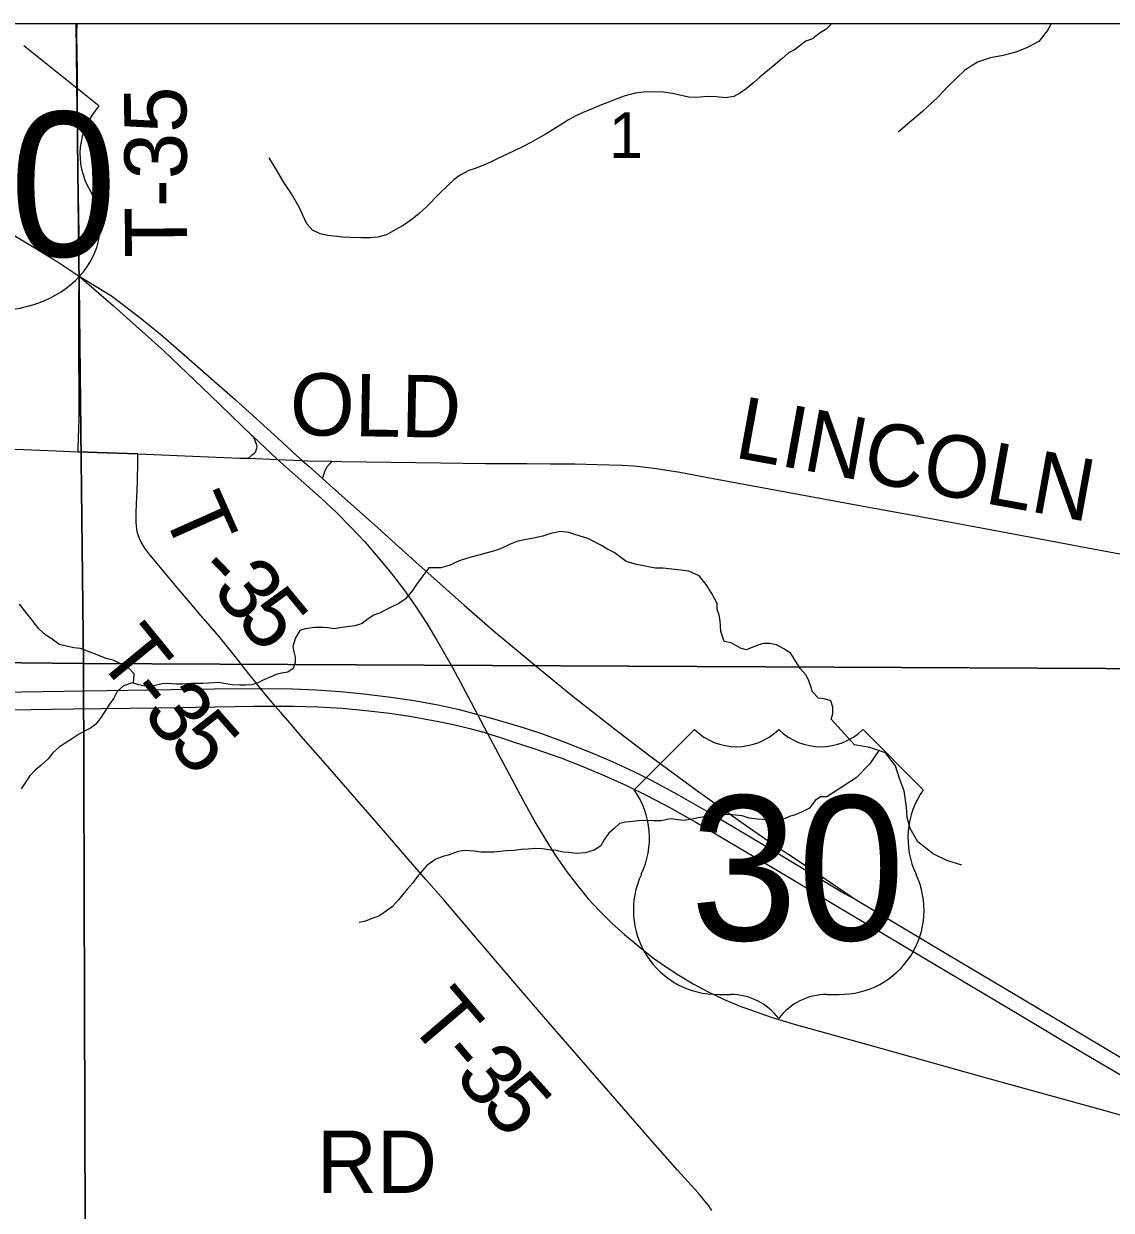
# Model space of a CAD drawing. Extents: x 0 to 34, y 0 to 22.
# Drawn here: x 4.726 to 5.719, y 19.817 to 20.9 of the extents above; entities that cross this region are included whole.
import ezdxf

# ---------------------------------------------------------------- set-up
doc = ezdxf.new("R2010")
doc.units = 0
for name, color, linetype in [('GM_X_County_Road', 7, 'Continuous'), ('GM_X_County_Road_Text', 7, 'Continuous'), ('GM_X_Interchange_Ramps', 7, 'Continuous'), ('GM_X_Minor_River', 7, 'Continuous'), ('GM_X_Section', 7, 'Continuous'), ('GM_X_Section_Text', 7, 'Continuous'), ('GM_X_Township_Road', 7, 'Continuous'), ('GM_X_Township_Road_Text', 7, 'Continuous'), ('GM_X_Unincorporated', 7, 'Continuous'), ('GM_X_US_Location', 7, 'Continuous'), ('GM_X_US_Route', 7, 'Continuous'), ('GM_X_US_Shield', 7, 'Continuous')]:
    doc.layers.add(name, color=color, linetype=linetype)

msp = doc.modelspace()

# ---------------------------------------------------------------- linework, layer by layer
at = {"layer": 'GM_X_County_Road'}
msp.add_line((4.9312, 20.5034), (4.9578, 20.5024), dxfattribs=at)
for points in [[(4.283, 20.4469), (4.286, 20.4472), (4.2983, 20.4487), (4.3168, 20.4517), (4.3473, 20.4574), (4.4482, 20.4752), (4.4727, 20.4795), (4.5308, 20.4898), (4.6012, 20.5021), (4.6318, 20.5072), (4.6503, 20.5097), (4.6657, 20.5113), (4.6812, 20.5121), (4.6967, 20.5123), (4.7184, 20.5117), (4.7556, 20.5101), (4.7757, 20.5094)], [(4.7757, 20.5094), (4.7929, 20.5087), (4.8304, 20.5074)], [(4.8304, 20.5074), (4.8519, 20.5066), (4.9233, 20.5036), (4.9312, 20.5034)], [(4.9578, 20.5024), (4.9802, 20.5013), (4.9853, 20.5011), (5.0077, 20.5007)], [(5.0077, 20.5007), (5.0164, 20.5005), (5.1065, 20.4993), (5.1476, 20.4987), (5.1695, 20.4986)], [(5.1695, 20.4986), (5.1854, 20.4986), (5.2065, 20.4983), (5.2294, 20.4982), (5.2496, 20.4977), (5.2723, 20.4972), (5.283, 20.4965), (5.2939, 20.4954), (5.3034, 20.4942), (5.3248, 20.4906), (5.3554, 20.485), (5.5022, 20.458), (5.5359, 20.4518), (5.6032, 20.4392), (5.6277, 20.4348), (5.7314, 20.4153), (5.7741, 20.4072), (5.7768, 20.4067)]]:
    msp.add_lwpolyline(points, dxfattribs=at)
at = {"layer": 'GM_X_Interchange_Ramps'}
for points in [[(4.9357, 20.5231), (4.937, 20.5197), (4.9383, 20.5165), (4.9388, 20.5142), (4.9385, 20.5124), (4.9375, 20.5095), (4.9358, 20.5072), (4.9341, 20.5058), (4.9312, 20.5034)], [(4.9989, 20.4848), (4.9994, 20.4865), (5.001, 20.4916), (5.0021, 20.494), (5.0034, 20.4961), (5.0057, 20.4985), (5.0077, 20.5007)]]:
    msp.add_lwpolyline(points, dxfattribs=at)
at = {"layer": 'GM_X_Minor_River'}
for points in [[(5.4632, 20.9), (5.4585, 20.8951), (5.452, 20.8909), (5.446, 20.8863), (5.4399, 20.884), (5.4297, 20.876), (5.424, 20.8733), (5.418, 20.868), (5.4101, 20.8611), (5.4033, 20.8557), (5.398, 20.8511), (5.3923, 20.8462), (5.3855, 20.8404), (5.3802, 20.837), (5.3741, 20.8335), (5.3666, 20.8324), (5.3582, 20.8331), (5.3499, 20.8334), (5.3434, 20.833), (5.3343, 20.8326), (5.3275, 20.8341), (5.3183, 20.8363), (5.31, 20.8374), (5.3009, 20.8378), (5.2922, 20.8374), (5.2842, 20.8366), (5.2751, 20.8342), (5.2675, 20.8315), (5.2607, 20.8288), (5.2535, 20.8258), (5.2455, 20.8227), (5.2368, 20.8188), (5.23, 20.8158), (5.2232, 20.8123), (5.2156, 20.8073), (5.2085, 20.8028), (5.202, 20.7989), (5.196, 20.7955), (5.1895, 20.792), (5.182, 20.7878), (5.1744, 20.7843), (5.1672, 20.7809), (5.1589, 20.7771), (5.1521, 20.7736), (5.1452, 20.7705), (5.138, 20.7678), (5.1324, 20.7659), (5.1244, 20.7617), (5.1191, 20.7579), (5.1127, 20.7517), (5.1059, 20.7453), (5.0938, 20.733), (5.087, 20.7269), (5.0802, 20.7212), (5.0723, 20.7158), (5.0651, 20.712), (5.0571, 20.7074), (5.0492, 20.7051), (5.0424, 20.7047), (5.034, 20.7046), (5.0241, 20.705), (5.0173, 20.7053), (5.012, 20.7057), (5.0036, 20.7068), (4.9968, 20.7083), (4.9896, 20.7116)], [(5.6634, 20.9), (5.6611, 20.8948), (5.6525, 20.8838), (5.6408, 20.8776), (5.6306, 20.8738), (5.62, 20.871), (5.6083, 20.8687), (5.5966, 20.8648), (5.5849, 20.8575), (5.5698, 20.843), (5.5601, 20.8326), (5.5465, 20.82), (5.5367, 20.8116), (5.5243, 20.8009)], [(4.9896, 20.7116), (4.9844, 20.7172), (4.9775, 20.7327), (4.9706, 20.7448), (4.9633, 20.7558), (4.9568, 20.7667), (4.95, 20.7777)], [(5.4842, 20.242), (5.4629, 20.2652), (5.4644, 20.2701), (5.4647, 20.2762), (5.4628, 20.2819), (5.4567, 20.2838), (5.4514, 20.2845), (5.446, 20.2902), (5.4445, 20.2951), (5.4426, 20.3004), (5.4403, 20.3054), (5.4349, 20.3111), (5.4307, 20.3179), (5.4261, 20.3251), (5.4204, 20.3292), (5.4132, 20.333), (5.4067, 20.3345), (5.4014, 20.3345), (5.3961, 20.3329), (5.3908, 20.3306), (5.3855, 20.3287), (5.3802, 20.3302), (5.3718, 20.3351), (5.3653, 20.3362), (5.3623, 20.3453), (5.3618, 20.3552), (5.3607, 20.3601), (5.3591, 20.3655), (5.3591, 20.3708), (5.3541, 20.3799), (5.3488, 20.3882), (5.3426, 20.3962), (5.3331, 20.4003), (5.3259, 20.4014), (5.3176, 20.4021), (5.3096, 20.4032), (5.3028, 20.4032), (5.2978, 20.404), (5.2902, 20.4054), (5.2853, 20.4066), (5.2758, 20.4092), (5.2651, 20.4175), (5.2583, 20.4209), (5.2533, 20.4239), (5.2408, 20.4303), (5.229, 20.4337), (5.2237, 20.4356), (5.2161, 20.4367), (5.2073, 20.4347), (5.1998, 20.4324), (5.1914, 20.4305), (5.185, 20.4293), (5.177, 20.4277), (5.1694, 20.4247), (5.1611, 20.4208), (5.1558, 20.4189), (5.149, 20.417), (5.1414, 20.415), (5.1334, 20.4127), (5.1262, 20.4108), (5.1213, 20.4089), (5.1153, 20.4058), (5.1069, 20.4035), (5.0959, 20.4034), (5.0895, 20.395), (5.0846, 20.3882), (5.0808, 20.3828), (5.0741, 20.3748), (5.0684, 20.371), (5.0616, 20.3675), (5.0567, 20.3652), (5.0514, 20.3625), (5.0457, 20.3602), (5.0404, 20.3568), (5.0351, 20.3526), (5.0283, 20.3506), (5.0211, 20.3495), (5.0146, 20.3487), (5.0097, 20.3479), (5.004, 20.3486), (4.9991, 20.349), (4.9915, 20.3489), (4.9831, 20.3478), (4.9782, 20.3462), (4.9741, 20.3394), (4.9718, 20.3317), (4.9726, 20.3268), (4.9738, 20.3219), (4.9738, 20.3169), (4.9719, 20.3116), (4.967, 20.3082), (4.9613, 20.3074), (4.9564, 20.3062), (4.9515, 20.3039), (4.9454, 20.3012)], [(4.8264, 20.298), (4.827, 20.3068), (4.8216, 20.3121), (4.8155, 20.3151), (4.8076, 20.3192), (4.8015, 20.3207), (4.7946, 20.3233), (4.7844, 20.3275), (4.7779, 20.3297), (4.7718, 20.3305), (4.765, 20.3319), (4.7585, 20.3334), (4.7517, 20.3387), (4.7463, 20.3421), (4.7398, 20.3478), (4.7337, 20.3558), (4.7223, 20.3702)], [(4.9454, 20.3012), (4.9397, 20.2985), (4.9344, 20.2966), (4.9287, 20.2962), (4.9234, 20.2962), (4.9162, 20.2965), (4.9109, 20.2976), (4.9041, 20.2987), (4.8946, 20.2983), (4.8896, 20.2979), (4.879, 20.2979), (4.8707, 20.2974), (4.8654, 20.2974), (4.8574, 20.2978), (4.8524, 20.2977), (4.8445, 20.2958), (4.8365, 20.2954), (4.8312, 20.2965), (4.8251, 20.2984), (4.8172, 20.2957), (4.8115, 20.2907), (4.8085, 20.2846), (4.8043, 20.2789), (4.801, 20.2739), (4.7968, 20.2671), (4.7919, 20.2606), (4.787, 20.2571), (4.7821, 20.2548), (4.776, 20.2514), (4.7696, 20.2472), (4.7639, 20.2434), (4.7586, 20.2399), (4.7526, 20.2346), (4.7484, 20.2292), (4.7416, 20.2231), (4.7367, 20.2189), (4.7314, 20.2132), (4.7281, 20.2082), (4.7239, 20.2017)], [(5.5823, 20.132), (5.5686, 20.1364), (5.5561, 20.1424), (5.542, 20.1533), (5.5351, 20.1654), (5.5324, 20.1756), (5.5319, 20.1851), (5.5296, 20.1999), (5.5257, 20.2104), (5.5218, 20.2226), (5.5127, 20.2346), (5.4982, 20.2394), (5.4842, 20.242)], [(5.5065, 20.2367), (5.498, 20.2243), (5.4859, 20.2117)], [(5.4859, 20.2117), (5.4591, 20.1944), (5.4534, 20.1944), (5.4485, 20.191), (5.4432, 20.1841), (5.436, 20.1803), (5.4303, 20.178), (5.425, 20.1764), (5.4189, 20.1737), (5.4125, 20.1729), (5.4064, 20.1729), (5.4007, 20.1736), (5.3954, 20.174), (5.3882, 20.1751), (5.3817, 20.177), (5.3757, 20.1777), (5.3688, 20.1784), (5.362, 20.1776), (5.3533, 20.1765), (5.3476, 20.1761), (5.3415, 20.1753), (5.3347, 20.1737), (5.3282, 20.1729), (5.3161, 20.1744), (5.3078, 20.1725), (5.3009, 20.1724), (5.2937, 20.1728), (5.2873, 20.1724), (5.2816, 20.172), (5.2755, 20.1712), (5.2698, 20.17), (5.2649, 20.1654), (5.26, 20.1612), (5.2562, 20.1559), (5.2528, 20.1498), (5.2468, 20.1459), (5.2388, 20.1432), (5.2305, 20.1428), (5.2237, 20.1436), (5.2183, 20.1439), (5.2119, 20.1454), (5.2069, 20.1458), (5.1997, 20.1469), (5.1933, 20.1472), (5.1864, 20.1468), (5.18, 20.1464), (5.1736, 20.1456), (5.1663, 20.1452), (5.1607, 20.1444), (5.1553, 20.144), (5.1436, 20.144), (5.1371, 20.1447), (5.128, 20.1454), (5.1227, 20.1446), (5.1136, 20.1412), (5.1087, 20.14), (5.1022, 20.1377), (5.0939, 20.1319), (5.0898, 20.127), (5.0853, 20.1213), (5.0811, 20.1159), (5.0762, 20.1102), (5.0721, 20.1052), (5.0683, 20.1003), (5.0626, 20.0945), (5.0551, 20.0888), (5.0501, 20.0854), (5.0433, 20.083), (5.038, 20.0811), (5.0323, 20.0796)]]:
    msp.add_lwpolyline(points, dxfattribs=at)
at = {"layer": 'GM_X_Section'}
for points in [[(4.783, 19.4891), (4.7808, 20.316), (3.7817, 20.3267), (3.7715, 19.4891)], [(5.415, 19.3104), (5.7798, 19.3134), (5.776, 20.2897), (5.7762, 20.3113), (4.7808, 20.316), (4.783, 19.4891), (5.415, 19.4891)]]:
    msp.add_lwpolyline(points, close=True, dxfattribs=at)
at = {"layer": 'GM_X_Township_Road'}
for points in [[(5.7764, 19.7938), (5.7766, 19.8909), (5.7765, 19.9131), (5.7764, 19.9288), (5.7766, 20.4072), (5.7818, 20.9), (2.1, 20.9)], [(4.7766, 20.6695), (4.7767, 20.7042), (4.7763, 20.7289), (4.7756, 20.7665), (4.7754, 20.7877), (4.7751, 20.8136), (4.7751, 20.8441), (4.7751, 20.858), (4.775, 20.8723), (4.7747, 20.8907), (4.7748, 20.9)], [(4.7757, 20.5094), (4.7758, 20.513), (4.7766, 20.5394), (4.7763, 20.6202), (4.7763, 20.6481), (4.7766, 20.6666), (4.7766, 20.6695)], [(4.8304, 20.5074), (4.7929, 20.5087), (4.7757, 20.5094)], [(4.9557, 20.2771), (4.9422, 20.2932), (4.9354, 20.3017), (4.9317, 20.3067), (4.9182, 20.3238), (4.9044, 20.3406), (4.8882, 20.3595), (4.8661, 20.3855), (4.8521, 20.4021), (4.8402, 20.4165), (4.8365, 20.4215), (4.8334, 20.4269), (4.832, 20.4297), (4.831, 20.4326), (4.8301, 20.4355), (4.8294, 20.4386), (4.8288, 20.4448), (4.8288, 20.4541), (4.83, 20.482), (4.8303, 20.5007), (4.8304, 20.5074)], [(5.354, 19.8169), (5.3532, 19.8184), (5.3523, 19.8198), (5.3516, 19.821), (5.3496, 19.8234), (5.3415, 19.8329), (5.3228, 19.8537), (5.2982, 19.8817), (5.2615, 19.9238), (5.237, 19.9519), (5.2227, 19.9683), (5.2044, 19.9894), (5.1761, 20.0224), (5.1337, 20.072), (5.1095, 20.1003), (5.0931, 20.1189), (5.0808, 20.1329), (5.0545, 20.1636), (5.0362, 20.1846), (5.0218, 20.201), (5.0036, 20.2221), (4.9811, 20.2478), (4.969, 20.262), (4.9609, 20.2714), (4.9557, 20.2771)]]:
    msp.add_lwpolyline(points, dxfattribs=at)
at = {"layer": 'GM_X_Unincorporated'}
for points in [[(4.7739, 20.9), (3.785, 20.9), (3.7817, 20.3267), (4.7808, 20.316)], [(5.7777, 20.9), (4.7739, 20.9), (4.7808, 20.316), (5.7762, 20.3113)]]:
    msp.add_lwpolyline(points, close=True, dxfattribs=at)
at = {"layer": 'GM_X_US_Route'}
for points in [[(4.258, 20.9), (4.2837, 20.89), (4.4135, 20.8396), (4.4602, 20.8211), (4.5062, 20.8035), (4.5612, 20.7819), (4.5956, 20.7677), (4.6184, 20.7577), (4.6437, 20.7459), (4.6684, 20.7334), (4.6879, 20.7233), (4.712, 20.7099), (4.7362, 20.6954), (4.7574, 20.6823), (4.772, 20.6725), (4.7766, 20.6695)], [(4.7766, 20.6695), (4.808, 20.6426), (4.8288, 20.6241), (4.8539, 20.6015), (4.8962, 20.5609), (4.9341, 20.5245), (4.9357, 20.5231), (4.9511, 20.5087), (4.9578, 20.5024), (4.9979, 20.4666), (5.0115, 20.4538), (5.0247, 20.4406), (5.0374, 20.427), (5.0497, 20.4129), (5.0616, 20.3985), (5.0729, 20.3836), (5.0836, 20.3683), (5.0939, 20.3527), (5.1035, 20.3367), (5.1173, 20.3124), (5.1316, 20.2857)], [(4.7766, 20.6695), (4.8062, 20.6515), (4.832, 20.632), (4.8511, 20.6165), (4.8676, 20.602), (4.919, 20.5569), (4.9579, 20.5218), (4.9751, 20.506), (4.9802, 20.5013), (4.9865, 20.4959), (4.9989, 20.4848), (5.0051, 20.4792), (5.0492, 20.4398), (5.0839, 20.4086), (5.1281, 20.3692), (5.1564, 20.3447), (5.1971, 20.3108), (5.2261, 20.2873), (5.2654, 20.2566), (5.2976, 20.232), (5.3402, 20.2005), (5.3807, 20.1715), (5.4064, 20.1538), (5.4406, 20.1313), (5.4849, 20.1009)], [(4.7043, 20.2901), (4.782, 20.2912), (4.9, 20.2929), (4.9422, 20.2932), (4.9435, 20.2932), (4.9715, 20.2929), (4.9932, 20.292), (5.0149, 20.2906), (5.0365, 20.2885), (5.0611, 20.2855), (5.0826, 20.2822), (5.104, 20.2783), (5.1222, 20.2744), (5.1282, 20.273), (5.1402, 20.2697), (5.1462, 20.2681), (5.1581, 20.2647), (5.1819, 20.2576), (5.1996, 20.2518), (5.22, 20.2444), (5.2431, 20.2353), (5.2631, 20.2268), (5.2829, 20.2177), (5.2995, 20.2093), (5.3241, 20.196), (5.3537, 20.179), (5.41, 20.1456), (5.4753, 20.1063), (5.4849, 20.1009), (5.5695, 20.0507), (5.6521, 20.0015), (5.7321, 19.9538)], [(5.1316, 20.2857), (5.1402, 20.2697), (5.1495, 20.2523), (5.1816, 20.1917), (5.1936, 20.17), (5.2031, 20.154), (5.2114, 20.1409), (5.2221, 20.1257), (5.2315, 20.1134), (5.2414, 20.1015), (5.2519, 20.09), (5.2629, 20.0791), (5.2743, 20.0687), (5.2886, 20.0568), (5.3008, 20.0473), (5.3109, 20.0401), (5.3239, 20.0316), (5.3372, 20.0238), (5.3509, 20.0165), (5.3649, 20.0099), (5.3792, 20.0038), (5.3937, 19.9984), (5.4084, 19.9934), (5.4292, 19.9871), (5.4919, 19.9695), (5.6056, 19.9378), (5.7094, 19.9091), (5.7352, 19.9018)], [(4.6749, 20.2733), (4.7712, 20.2746), (4.8489, 20.2756), (4.9359, 20.2771), (4.9557, 20.2771), (4.9573, 20.2771), (4.9732, 20.2771), (4.9949, 20.2766), (5.0167, 20.2753), (5.0384, 20.2733), (5.06, 20.2707), (5.0784, 20.2679), (5.0999, 20.2641), (5.1047, 20.2631)], [(5.1047, 20.2631), (5.1182, 20.2603), (5.1333, 20.2568), (5.1444, 20.2539)], [(5.1444, 20.2539), (5.1454, 20.2536), (5.1495, 20.2523), (5.1602, 20.2489), (5.172, 20.245), (5.1927, 20.2383), (5.2162, 20.23), (5.2365, 20.2222), (5.2565, 20.2137), (5.2763, 20.2047), (5.2959, 20.1951), (5.3151, 20.1849), (5.3395, 20.1712), (5.4224, 20.1222), (5.4704, 20.0934), (5.636, 19.9949), (5.6893, 19.963), (5.7483, 19.9284), (5.7726, 19.9147), (5.7767, 19.9125)]]:
    msp.add_lwpolyline(points, dxfattribs=at)
at = {"layer": 'GM_X_US_Shield'}
for p, q in [((4.7948, 20.8249), (4.7261, 20.8799)), ((5.3382, 20.2558), (5.2833, 20.2009)), ((5.547, 20.2009), (5.4921, 20.2558)), ((5.3602, 20.0141), (5.3712, 20.0141)), ((5.4591, 20.0141), (5.4701, 20.0141))]:
    msp.add_line(p, q, dxfattribs=at)
for centre, radius, start, end in [((5.3767, 20.2951), 0.0549, 225.573, 314.427), ((5.4536, 20.2951), 0.0549, 225.573, 314.427), ((5.2203, 20.1568), 0.0769, 334.5471, 35.0009), ((5.61, 20.1568), 0.0769, 144.9991, 205.4529), ((5.3594, 20.091), 0.0769, 154.8319, 270.6383), ((5.4709, 20.091), 0.0769, 269.3617, 25.1681), ((5.3712, 19.9592), 0.0549, 36.8699, 90), ((5.4591, 19.9592), 0.0549, 90, 143.1301)]:
    msp.add_arc(centre, radius, start, end, dxfattribs=at)
for centre, start_param, end_param in [((4.8735, 20.7808), 5.672304, 6.727422), ((4.6997, 20.7151), 1.559657, 3.580859)]:
    msp.add_ellipse(centre, major_axis=(-0.0961, 0), ratio=0.8, start_param=start_param, end_param=end_param, dxfattribs=at)

# ---------------------------------------------------------------- texts
at = {"layer": 'GM_X_County_Road_Text'}
for s, rotation, p in [('OLD', 359.0196, (4.9687, 20.5246)), ('LINCOLN', 349.667, (5.3734, 20.5043))]:
    msp.add_text(s, height=0.05682, rotation=rotation, dxfattribs=at).set_placement(p)
at = {"layer": 'GM_X_Section_Text'}
msp.add_text('1', height=0.0419, rotation=0, dxfattribs=at).set_placement((5.2602, 20.7773))
at = {"layer": 'GM_X_Township_Road_Text'}
for s, height, rotation, p in [('T-35', 0.05682, 90.3515, (4.8754, 20.6865)), ('T', 0.0568, 294.0223, (4.8518, 20.455)), ('-', 0.0568, 314.5706, (4.8815, 20.398)), ('3', 0.0568, 309.8202, (4.8969, 20.3824)), ('5', 0.0568, 309.4495, (4.919, 20.3558)), ('T', 0.0568, 309.2418, (4.7913, 20.3216)), ('-', 0.0568, 309.334, (4.8182, 20.2886)), ('3', 0.0568, 309.7271, (4.8333, 20.2702)), ('5', 0.0568, 311.3284, (4.8568, 20.242)), ('T', 0.0568, 310.4709, (5.0751, 19.9891)), ('-', 0.0568, 310.5362, (5.1028, 19.9567)), ('3', 0.0568, 310.8256, (5.1181, 19.9388)), ('5', 0.0568, 312.0874, (5.1419, 19.9113)), ('RD', 0.05682, 0, (4.9935, 19.833))]:
    msp.add_text(s, height=height, rotation=rotation, dxfattribs=at).set_placement(p)
at = {"layer": 'GM_X_US_Location'}
for s in ['0', '/']:
    msp.add_text(s, height=0.000189, dxfattribs=at).set_placement((5.4151, 20.1284))
msp.add_text('30', height=0.000189, rotation=0, dxfattribs=at).set_placement((5.376, 20.0892))
at = {"layer": 'GM_X_US_Shield'}
for s, p in [('250', (4.5172, 20.6876)), ('30', (5.3343, 20.0636))]:
    msp.add_text(s, height=0.13184, dxfattribs=at).set_placement(p)

doc.saveas('drawing.dxf')
